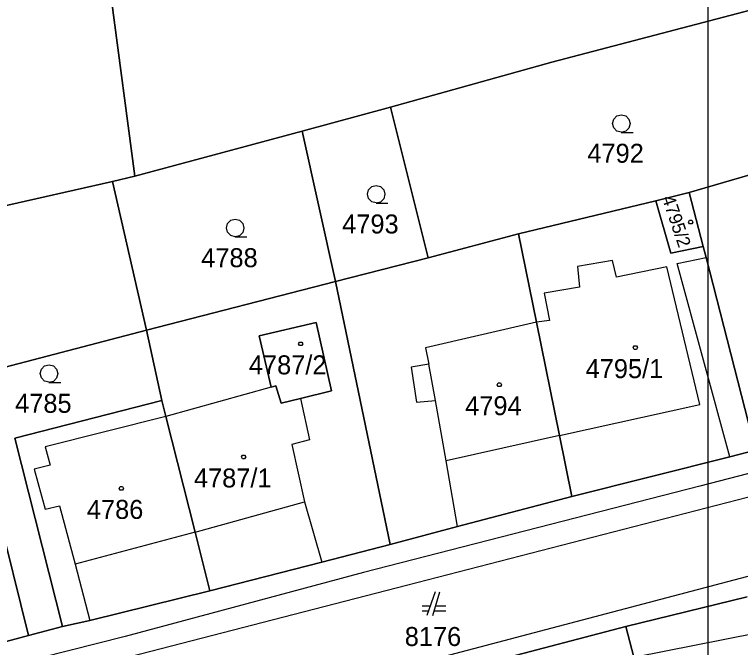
# Model space of a CAD drawing. Extents: x -263587 to -261993, y -1238795 to -1236748.
# Drawn here: x -262753.5 to -262692.3, y -1238057.9 to -1238004.5 of the extents above; entities that cross this region are included whole.
import ezdxf

# ---------------------------------------------------------------- set-up
doc = ezdxf.new("R2010")
doc.units = 0
doc.layers.add('Vrstva 1', color=7, linetype='Continuous')
doc.layers.add('Vrstva 51', color=7, linetype='Continuous')

msp = doc.modelspace()

# ---------------------------------------------------------------- linework, layer by layer
at = {"layer": 'Vrstva 1'}
for p, q in [((-262743.34, -1238018.15), (-262746.28, -1237995.66)), ((-262746.28, -1237995.66), (-262743.34, -1238018.15)), ((-262708.17, -1238008.54), (-262690.29, -1238003.86)), ((-262690.29, -1238003.86), (-262708.17, -1238008.54)), ((-262721.77, -1238012.34), (-262708.17, -1238008.54)), ((-262708.17, -1238008.54), (-262721.77, -1238012.34)), ((-262729.23, -1238014.35), (-262721.77, -1238012.34)), ((-262721.77, -1238012.34), (-262729.23, -1238014.35)), ((-262718.6, -1238025.03), (-262721.77, -1238012.34)), ((-262721.77, -1238012.34), (-262718.6, -1238025.03)), ((-262743.34, -1238018.15), (-262729.23, -1238014.35)), ((-262729.23, -1238014.35), (-262743.34, -1238018.15)), ((-262729.23, -1238014.35), (-262726.4, -1238027.04)), ((-262726.4, -1238027.04), (-262729.23, -1238014.35)), ((-262696.58, -1238019.54), (-262687.02, -1238016.74)), ((-262687.02, -1238016.74), (-262696.58, -1238019.54)), ((-262770.42, -1238024.24), (-262745.2, -1238018.61)), ((-262745.2, -1238018.61), (-262770.42, -1238024.24)), ((-262745.2, -1238018.61), (-262743.34, -1238018.15)), ((-262743.34, -1238018.15), (-262745.2, -1238018.61)), ((-262742.34, -1238031.14), (-262745.2, -1238018.61)), ((-262745.2, -1238018.61), (-262742.34, -1238031.14)), ((-262699.39, -1238020.24), (-262696.58, -1238019.54)), ((-262696.58, -1238019.54), (-262699.39, -1238020.24)), ((-262696.58, -1238019.54), (-262695.4, -1238024.09)), ((-262695.4, -1238024.09), (-262696.58, -1238019.54)), ((-262710.99, -1238023.01), (-262699.39, -1238020.24)), ((-262699.39, -1238020.24), (-262710.99, -1238023.01)), ((-262699.39, -1238020.24), (-262698.15, -1238024.65)), ((-262698.15, -1238024.65), (-262699.39, -1238020.24)), ((-262718.6, -1238025.03), (-262710.99, -1238023.01)), ((-262710.99, -1238023.01), (-262718.6, -1238025.03)), ((-262710.99, -1238023.01), (-262709.47, -1238030.44)), ((-262709.47, -1238030.44), (-262710.99, -1238023.01)), ((-262698.15, -1238024.65), (-262695.4, -1238024.09)), ((-262695.4, -1238024.09), (-262698.15, -1238024.65)), ((-262695.4, -1238024.09), (-262695.17, -1238024.99)), ((-262695.17, -1238024.99), (-262695.4, -1238024.09)), ((-262726.4, -1238027.04), (-262718.6, -1238025.03)), ((-262718.6, -1238025.03), (-262726.4, -1238027.04)), ((-262703.05, -1238025.26), (-262706.01, -1238025.76)), ((-262702.71, -1238026.67), (-262703.05, -1238025.26)), ((-262697.6, -1238025.52), (-262695.17, -1238024.99)), ((-262695.17, -1238024.99), (-262690.99, -1238041.24)), ((-262690.99, -1238041.24), (-262695.17, -1238024.99)), ((-262706.01, -1238025.76), (-262705.83, -1238027.49)), ((-262698.47, -1238025.78), (-262702.71, -1238026.67)), ((-262695.7, -1238037.38), (-262698.47, -1238025.78)), ((-262693.16, -1238041.79), (-262697.6, -1238025.52)), ((-262742.34, -1238031.14), (-262726.4, -1238027.04)), ((-262726.4, -1238027.04), (-262742.34, -1238031.14)), ((-262721.79, -1238049.18), (-262726.4, -1238027.04)), ((-262726.4, -1238027.04), (-262721.79, -1238049.18)), ((-262705.83, -1238027.49), (-262708.82, -1238028)), ((-262708.82, -1238028), (-262708.36, -1238030.3)), ((-262728.04, -1238030.48), (-262732.85, -1238031.6)), ((-262732.85, -1238031.6), (-262728.04, -1238030.48)), ((-262726.74, -1238036.25), (-262728.04, -1238030.48)), ((-262728.04, -1238030.48), (-262726.74, -1238036.25)), ((-262709.47, -1238030.44), (-262718.81, -1238032.61)), ((-262708.36, -1238030.3), (-262709.47, -1238030.44)), ((-262709.47, -1238030.44), (-262707.51, -1238040.01)), ((-262707.51, -1238040.01), (-262709.47, -1238030.44)), ((-262757.73, -1238035.13), (-262742.34, -1238031.14)), ((-262742.34, -1238031.14), (-262757.73, -1238035.13)), ((-262741.05, -1238037.06), (-262742.34, -1238031.14)), ((-262742.34, -1238031.14), (-262741.05, -1238037.06)), ((-262732.85, -1238031.6), (-262731.82, -1238035.92)), ((-262731.82, -1238035.92), (-262732.85, -1238031.6)), ((-262718.81, -1238032.61), (-262718.55, -1238033.99)), ((-262718.55, -1238033.99), (-262720.04, -1238034.24)), ((-262720.04, -1238034.24), (-262719.58, -1238037.2)), ((-262717.97, -1238037.04), (-262718.55, -1238033.99)), ((-262656.29, -1238034.17), (-262695.7, -1238044.27)), ((-262731.82, -1238035.92), (-262740.71, -1238038.39)), ((-262731.82, -1238035.92), (-262731.44, -1238035.81)), ((-262731.44, -1238035.81), (-262731.82, -1238035.92)), ((-262731.44, -1238035.81), (-262730.98, -1238037.27)), ((-262730.98, -1238037.27), (-262731.44, -1238035.81)), ((-262729.37, -1238036.88), (-262726.74, -1238036.25)), ((-262726.74, -1238036.25), (-262729.37, -1238036.88)), ((-262655.81, -1238035.98), (-262720.41, -1238052.64)), ((-262730.98, -1238037.27), (-262729.37, -1238036.88)), ((-262729.37, -1238036.88), (-262730.98, -1238037.27)), ((-262729.37, -1238036.88), (-262728.6, -1238040.36)), ((-262741.05, -1238037.06), (-262753.45, -1238040.23)), ((-262753.45, -1238040.23), (-262741.05, -1238037.06)), ((-262740.71, -1238038.39), (-262741.05, -1238037.06)), ((-262741.05, -1238037.06), (-262740.71, -1238038.39)), ((-262719.58, -1238037.2), (-262717.97, -1238037.04)), ((-262717.08, -1238042.15), (-262717.97, -1238037.04)), ((-262707.51, -1238040.01), (-262695.7, -1238037.38)), ((-262740.71, -1238038.39), (-262750.88, -1238040.97)), ((-262738.25, -1238048.15), (-262740.71, -1238038.39)), ((-262740.71, -1238038.39), (-262738.25, -1238048.15)), ((-262707.51, -1238040.01), (-262717.08, -1238042.15)), ((-262707.51, -1238040.01), (-262706.47, -1238045.13)), ((-262706.47, -1238045.13), (-262707.51, -1238040.01)), ((-262753.45, -1238040.23), (-262749.43, -1238056.1)), ((-262749.43, -1238056.1), (-262753.45, -1238040.23)), ((-262728.6, -1238040.36), (-262730.08, -1238040.76)), ((-262750.88, -1238040.97), (-262750.47, -1238042.49)), ((-262730.08, -1238040.76), (-262729.01, -1238045.59)), ((-262690.99, -1238041.24), (-262693.16, -1238041.79)), ((-262693.16, -1238041.79), (-262690.99, -1238041.24)), ((-262756.15, -1238041.34), (-262752.3, -1238056.86)), ((-262752.3, -1238056.86), (-262756.15, -1238041.34)), ((-262693.16, -1238041.79), (-262706.47, -1238045.13)), ((-262706.47, -1238045.13), (-262693.16, -1238041.79)), ((-262750.47, -1238042.49), (-262751.8, -1238042.84)), ((-262654.73, -1238042.16), (-262723.17, -1238060.18)), ((-262716.12, -1238047.68), (-262717.08, -1238042.15)), ((-262751.8, -1238042.84), (-262750.88, -1238046.21)), ((-262695.7, -1238044.27), (-262724.05, -1238051.56)), ((-262706.47, -1238045.13), (-262716.12, -1238047.68)), ((-262716.12, -1238047.68), (-262706.47, -1238045.13)), ((-262750.88, -1238046.21), (-262749.67, -1238045.93)), ((-262749.67, -1238045.93), (-262748.37, -1238050.84)), ((-262738.24, -1238048.15), (-262729.01, -1238045.59)), ((-262729.01, -1238045.59), (-262727.57, -1238050.67)), ((-262716.12, -1238047.68), (-262721.79, -1238049.18)), ((-262721.79, -1238049.18), (-262716.12, -1238047.68)), ((-262738.25, -1238048.15), (-262748.37, -1238050.84)), ((-262738.24, -1238048.15), (-262738.25, -1238048.15)), ((-262738.25, -1238048.15), (-262738.24, -1238048.15)), ((-262736.99, -1238053.1), (-262738.24, -1238048.15)), ((-262738.24, -1238048.15), (-262736.99, -1238053.1)), ((-262721.79, -1238049.18), (-262727.57, -1238050.67)), ((-262727.57, -1238050.67), (-262721.79, -1238049.18)), ((-262748.37, -1238050.84), (-262747.13, -1238055.6)), ((-262727.57, -1238050.67), (-262736.99, -1238053.1)), ((-262736.99, -1238053.1), (-262727.57, -1238050.67)), ((-262724.05, -1238051.56), (-262744.14, -1238056.94)), ((-262720.41, -1238052.64), (-262807.94, -1238075.17)), ((-262736.99, -1238053.1), (-262747.13, -1238055.6)), ((-262747.13, -1238055.6), (-262736.99, -1238053.1)), ((-262718.01, -1238053.17), (-262718.71, -1238055.17)), ((-262718.21, -1238055.17), (-262717.61, -1238053.17)), ((-262701.92, -1238056.1), (-262691.71, -1238053.59)), ((-262691.71, -1238053.59), (-262701.92, -1238056.1)), ((-262718.43, -1238054.37), (-262719.11, -1238054.37)), ((-262717.11, -1238054.37), (-262717.97, -1238054.37)), ((-262719.11, -1238054.77), (-262718.57, -1238054.77)), ((-262718.09, -1238054.77), (-262717.11, -1238054.77)), ((-262747.13, -1238055.6), (-262749.43, -1238056.1)), ((-262749.43, -1238056.1), (-262747.13, -1238055.6)), ((-262749.43, -1238056.1), (-262752.3, -1238056.86)), ((-262752.3, -1238056.86), (-262749.43, -1238056.1)), ((-262701.92, -1238056.1), (-262712.86, -1238058.96)), ((-262712.86, -1238058.96), (-262701.92, -1238056.1)), ((-262701.26, -1238058.68), (-262701.92, -1238056.1)), ((-262701.92, -1238056.1), (-262701.26, -1238058.68)), ((-262744.14, -1238056.94), (-262808.62, -1238073.15)), ((-262752.3, -1238056.86), (-262767.67, -1238060.88)), ((-262767.67, -1238060.88), (-262752.3, -1238056.86)), ((-262701.26, -1238058.68), (-262690.89, -1238056.62))]:
    msp.add_line(p, q, dxfattribs=at)
for points in [[(-262702.3, -1238014.45), (-262702.68, -1238014.35), (-262702.95, -1238014.08), (-262703.05, -1238013.71), (-262702.95, -1238013.34), (-262702.68, -1238013.07), (-262702.31, -1238012.97), (-262701.94, -1238013.07), (-262701.67, -1238013.34), (-262701.57, -1238013.72), (-262701.67, -1238014.1), (-262701.94, -1238014.37), (-262702.32, -1238014.47), (-262701.32, -1238014.47)], [(-262722.97, -1238020.41), (-262723.35, -1238020.31), (-262723.62, -1238020.04), (-262723.72, -1238019.67), (-262723.62, -1238019.3), (-262723.35, -1238019.03), (-262722.98, -1238018.93), (-262722.61, -1238019.03), (-262722.34, -1238019.3), (-262722.24, -1238019.68), (-262722.34, -1238020.06), (-262722.61, -1238020.33), (-262722.99, -1238020.43), (-262721.99, -1238020.43)], [(-262734.86, -1238023.25), (-262735.24, -1238023.15), (-262735.51, -1238022.88), (-262735.61, -1238022.51), (-262735.51, -1238022.14), (-262735.24, -1238021.87), (-262734.87, -1238021.77), (-262734.5, -1238021.87), (-262734.23, -1238022.14), (-262734.13, -1238022.52), (-262734.23, -1238022.9), (-262734.5, -1238023.17), (-262734.88, -1238023.27), (-262733.88, -1238023.27)], [(-262750.55, -1238035.52), (-262750.93, -1238035.42), (-262751.2, -1238035.15), (-262751.3, -1238034.78), (-262751.2, -1238034.41), (-262750.93, -1238034.14), (-262750.56, -1238034.04), (-262750.19, -1238034.14), (-262749.92, -1238034.41), (-262749.82, -1238034.79), (-262749.92, -1238035.17), (-262750.19, -1238035.44), (-262750.57, -1238035.54), (-262749.57, -1238035.54)]]:
    msp.add_lwpolyline(points, dxfattribs=at)
for points in [[(-262696.37, -1238021.87), (-262696.28, -1238022.02), (-262696.37, -1238022.17), (-262696.55, -1238022.17), (-262696.64, -1238022.02), (-262696.55, -1238021.87)], [(-262729.25, -1238032.13), (-262729.16, -1238032.28), (-262729.25, -1238032.43), (-262729.43, -1238032.43), (-262729.52, -1238032.28), (-262729.43, -1238032.13)], [(-262701.04, -1238032.45), (-262700.95, -1238032.6), (-262701.04, -1238032.75), (-262701.22, -1238032.75), (-262701.31, -1238032.6), (-262701.22, -1238032.45)], [(-262712.51, -1238035.57), (-262712.42, -1238035.72), (-262712.51, -1238035.87), (-262712.69, -1238035.87), (-262712.78, -1238035.72), (-262712.69, -1238035.57)], [(-262734.07, -1238041.66), (-262733.98, -1238041.81), (-262734.07, -1238041.96), (-262734.25, -1238041.96), (-262734.34, -1238041.81), (-262734.25, -1238041.66)], [(-262744.37, -1238044.31), (-262744.28, -1238044.46), (-262744.37, -1238044.61), (-262744.55, -1238044.61), (-262744.64, -1238044.46), (-262744.55, -1238044.31)]]:
    msp.add_lwpolyline(points, close=True, dxfattribs=at)
at = {"layer": 'Vrstva 51'}
msp.add_lwpolyline([(-262992.03, -1237088.09), (-262695.03, -1237088.09), (-262695.03, -1238768.09), (-262992.03, -1238768.09)], close=True, dxfattribs=at)

# ---------------------------------------------------------------- texts
at = {"layer": 'Vrstva 1'}
for s, p in [('4792', (-262705.174, -1238017.02)), ('4793', (-262725.844, -1238022.98)), ('4788', (-262737.728, -1238025.82)), ('4787/2', (-262733.713, -1238034.85)), ('4795/1', (-262705.32, -1238035.17)), ('4785', (-262753.418, -1238038.09)), ('4794', (-262715.474, -1238038.29)), ('4787/1', (-262738.344, -1238044.38)), ('4786', (-262747.372, -1238047.03)), ('8176', (-262720.568, -1238057.74))]:
    msp.add_text(s, height=1.6, dxfattribs=at).set_placement(p)
msp.add_text('4795/2', height=1.1, rotation=288.71343, dxfattribs=at).set_placement((-262698.9, -1238019.991))

doc.saveas('drawing.dxf')
